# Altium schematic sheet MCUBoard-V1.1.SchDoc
size A; SheetNumber: 1; SheetTotal: 1
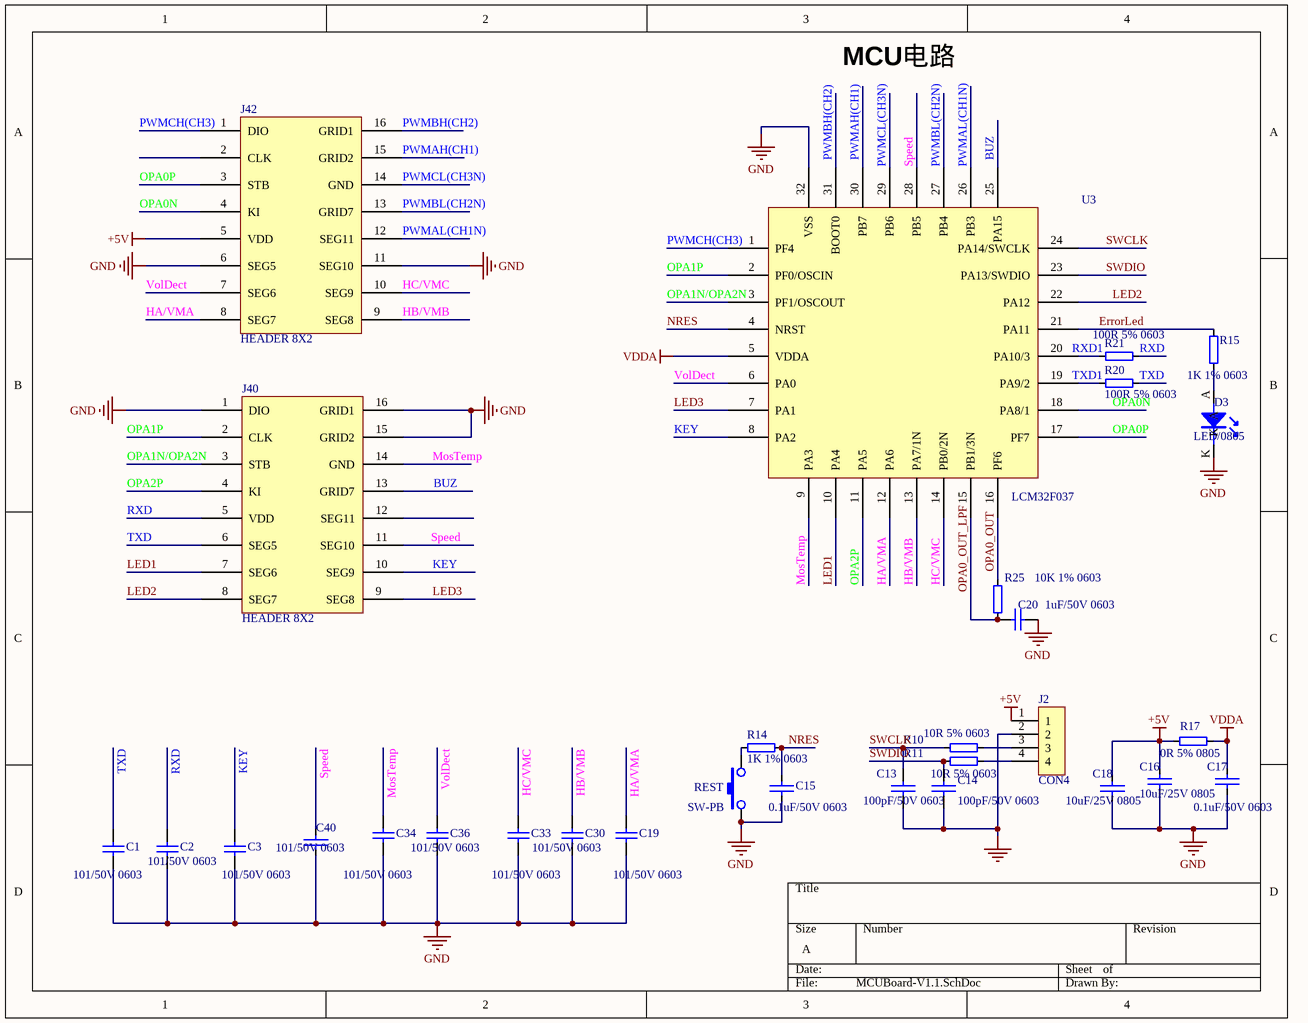
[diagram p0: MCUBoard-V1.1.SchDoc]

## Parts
C1  101/50V 0603  [0603C]
C2  101/50V 0603  [0603C]
C3  101/50V 0603  [0603C]
C13  100pF/50V 0603  [0603C]
C14  100pF/50V 0603  [0603C]
C15  0.1uF/50V 0603  [0603C]
C16  10uF/25V 0805  [0805C]
C17  0.1uF/50V 0603  [0603C]
C18  10uF/25V 0805  [0805C]
C19  101/50V 0603  [0603C]
C20  1uF/50V 0603  [0603C]
C30  101/50V 0603  [0603C]
C33  101/50V 0603  [0603C]
C34  101/50V 0603  [0603C]
C36  101/50V 0603  [0603C]
C40  101/50V 0603  [0603C]
D3  LED/0805  [0805/LED]
J2  CON4  [SIP4]
J40  HEADER 8X2  [DIP16-2]
J42  HEADER 8X2  [DIP16-2]
R10  10R 5% 0603  [0603R]
R11  10R 5% 0603  [0603R]
R14  1K 1% 0603  [0603R]
R15  1K 1% 0603  [0603R]
R17  0R 5% 0805  [R0805]
R20  100R 5% 0603  [0603R]
R21  100R 5% 0603  [0603R]
R25  10K 1% 0603  [0603R]
REST  SW-PB  [SP-SMT6*6*5]
U3  LCM32F037  [QFP32L]

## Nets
+5V: C16.1 C18.1 J2.1 J42.5(VDD) R17.2
GND: C1.1 C2.1 C3.1 C13.1 C14.1 C15.2 C16.2 C17.2 C18.2 C19.1 C20.1 C30.1 C33.1 C34.1 C36.1 C40.2 D3.K J2.2 J40.1(DIO) J40.15(GRID2) J40.16(GRID1) J42.6(SEG5) J42.11(SEG10) REST.2 U3.32(VSS)
VDDA: C17.1 R17.1 U3.5(VDDA)
BUZ: J40.13(GRID7) U3.25(PA15)
ErrorLed: R15.2 U3.21(PA11)
HA/VMA: C19.2 J42.8(SEG7) U3.12(PA6)
HB/VMB: C30.2 J42.9(SEG8) U3.13(PA7/1N)
HC/VMC: C33.2 J42.10(SEG9) U3.14(PB0/2N)
KEY: C3.2 J40.10(SEG9) U3.8(PA2)
LED1: J40.7(SEG6) U3.10(PA4)
LED2: J40.8(SEG7) U3.22(PA12)
LED3: J40.9(SEG8) U3.7(PA1)
MosTemp: C34.2 J40.14(GND) U3.9(PA3)
NRES: C15.1 R14.2 U3.4(NRST)
OPA0_OUT: R25.1 U3.16(PF6)
OPA0_OUT_LPF: C20.2 R25.2 U3.15(PB1/3N)
OPA0N: J42.4(KI) U3.18(PA8/1)
OPA0P: J42.3(STB) U3.17(PF7)
OPA1N/OPA2N: J40.3(STB) U3.3(PF1/OSCOUT)
OPA1P: J40.2(CLK) U3.2(PF0/OSCIN)
OPA2P: J40.4(KI) U3.11(PA5)
PWMAH(CH1): J42.15(GRID2) U3.30(PB7)
PWMAL(CH1N): J42.12(SEG11) U3.26(PB3)
PWMBH(CH2): J42.16(GRID1) U3.31(BOOT0)
PWMBL(CH2N): J42.13(GRID7) U3.27(PB4)
PWMCH(CH3): J42.1(DIO) U3.1(PF4)
PWMCL(CH3N): J42.14(GND) U3.29(PB6)
RXD: C2.2 J40.5(VDD) R21.2
Speed: C40.1 J40.11(SEG10) U3.28(PB5)
SWCLK: C13.2 R10.2 U3.24(PA14/SWCLK)
SWDIO: C14.2 R11.2 U3.23(PA13/SWDIO)
TXD: C1.2 J40.6(SEG5) R20.2
VolDect: C36.2 J42.7(SEG6) U3.6(PA0)
NetD3_A: D3.A R15.1
NetJ2_3: J2.3 R10.1
NetJ2_4: J2.4 R11.1
NetR14_1: R14.1 REST.1
NetR20_1: R20.1 U3.19(PA9/2)
NetR21_1: R21.1 U3.20(PA10/3)

Not connected (* = marked no-connect by the designer): J40 12(SEG11); J42 2(CLK)

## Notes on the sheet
- MCU电路
- Labels drawn without touching a wire or pin: RXD1, TXD1

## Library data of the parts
C1-C3 C19 = CAP: Capacitor; Value: 103/50V
C13 C14 C30 C33 C36 = CAP: Capacitor
C15-C18 C40 = CAP
C20 C34 = CAP: Capacitor; Value: 104/50V
D3 = LED
J40 J42 = TM1617
R10 R11 R14 R15 R17 R20 R21 R25 = RES
U3 = LCM32F030H8T6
